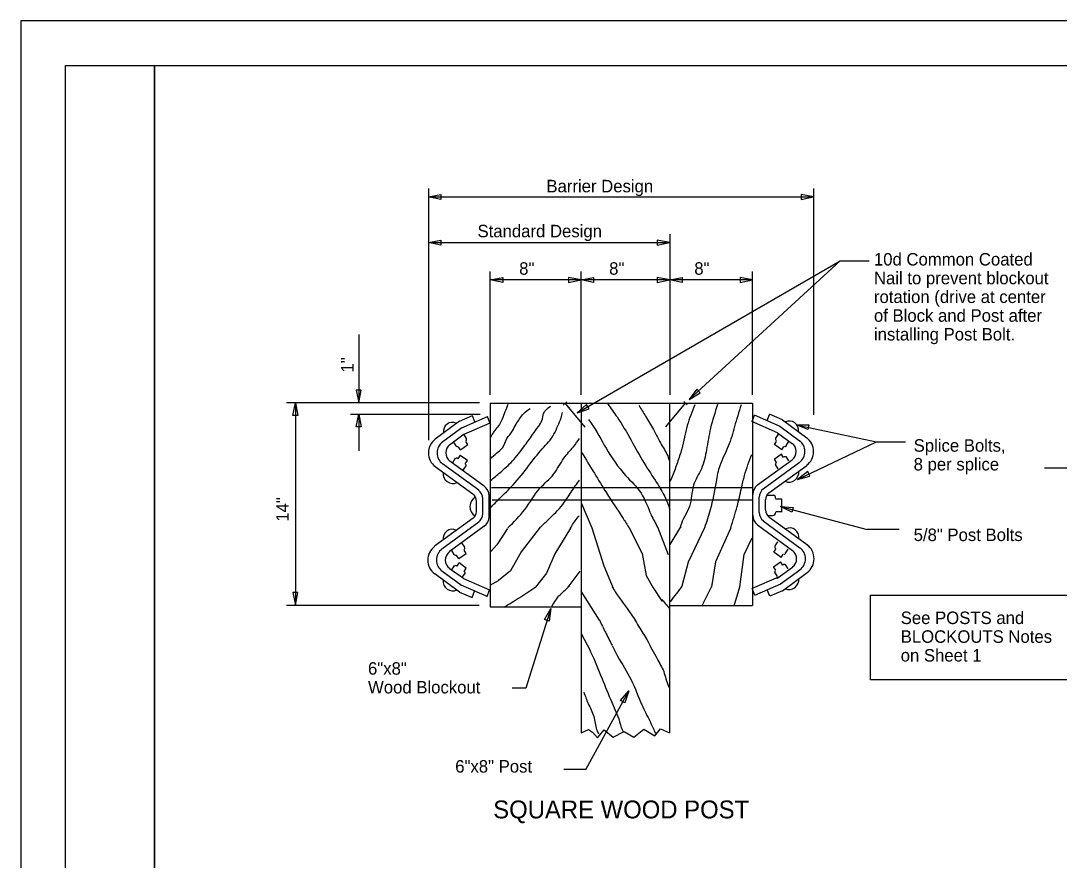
# Model space of a CAD drawing. Extents: x 0 to 34, y 0 to 22.
# Drawn here: x 0 to 11.64, y 12.6 to 22 of the extents above; entities that cross this region are included whole.
import ezdxf

# ---------------------------------------------------------------- set-up
doc = ezdxf.new("R2010")
doc.units = 0
for name, color, linetype in [('SH_Border', 7, 'Continuous'), ('SH_Cut_Line', 7, 'Continuous'), ('ST_Details', 7, 'Continuous'), ('ST_Text', 7, 'Continuous')]:
    doc.layers.add(name, color=color, linetype=linetype)

msp = doc.modelspace()

# ---------------------------------------------------------------- linework, layer by layer
at = {"layer": 'SH_Border'}
for points in [[(0.5, 21.5), (1.5, 21.5), (1.5, 0.5), (0.5, 0.5)], [(1.5, 21.5), (33.5, 21.5), (33.5, 0.5), (1.5, 0.5)]]:
    msp.add_lwpolyline(points, close=True, dxfattribs=at)
at = {"layer": 'SH_Cut_Line'}
msp.add_lwpolyline([(0, 0), (34, 0), (34, 22), (0, 22)], close=True, dxfattribs=at)
at = {"layer": 'ST_Details'}
for p, q in [((5.261, 17.716), (8.2, 17.716)), ((5.261, 17.716), (5.261, 15.435)), ((6.117, 17.731), (6.076, 17.694)), ((6.099, 17.712), (6.32, 17.447)), ((6.279, 17.716), (6.279, 14.022)), ((7.446, 17.717), (7.226, 17.452)), ((7.271, 17.716), (7.271, 14.022)), ((7.428, 17.736), (7.469, 17.699)), ((8.2, 17.716), (8.2, 15.448)), ((4.916, 17.513), (5.06, 17.576)), ((5.088, 17.506), (5.061, 17.575)), ((8.194, 17.511), (8.221, 17.581)), ((8.51, 17.455), (8.22, 17.582)), ((8.363, 17.521), (8.39, 17.59)), ((8.534, 17.528), (8.39, 17.591)), ((4.917, 17.513), (4.644, 17.313)), ((4.941, 17.44), (5.231, 17.566)), ((4.97, 17.369), (5.26, 17.496)), ((5.257, 17.496), (5.23, 17.565)), ((8.48, 17.385), (8.191, 17.511)), ((8.507, 17.457), (8.737, 17.288)), ((8.534, 17.528), (8.807, 17.328)), ((4.944, 17.441), (4.714, 17.273)), ((4.969, 17.369), (4.803, 17.247)), ((4.994, 17.321), (4.964, 17.368)), ((8.461, 17.323), (8.491, 17.37)), ((8.481, 17.384), (8.648, 17.262)), ((4.878, 17.238), (4.849, 17.284)), ((4.927, 17.192), (4.904, 17.228)), ((4.927, 17.192), (5.009, 17.251)), ((5.009, 17.251), (4.986, 17.286)), ((8.446, 17.253), (8.468, 17.288)), ((8.528, 17.194), (8.446, 17.253)), ((8.528, 17.194), (8.551, 17.23)), ((8.577, 17.24), (8.606, 17.286)), ((4.901, 17.093), (4.926, 17.132)), ((5.004, 17.074), (4.925, 17.131)), ((8.443, 17.089), (8.522, 17.146)), ((8.546, 17.108), (8.522, 17.147)), ((8.606, 17.068), (8.575, 17.118)), ((5.067, 16.696), (4.644, 17.004)), ((5.131, 16.741), (4.727, 17.035)), ((5.194, 16.786), (4.809, 17.066)), ((4.841, 17.053), (4.873, 17.103)), ((4.959, 16.967), (4.99, 17.015)), ((4.98, 17.035), (5.004, 17.073)), ((8.257, 16.801), (8.642, 17.081)), ((8.32, 16.756), (8.724, 17.05)), ((8.383, 16.711), (8.807, 17.019)), ((8.468, 17.051), (8.444, 17.088)), ((8.488, 16.982), (8.457, 17.03)), ((5.276, 16.77), (8.201, 16.77)), ((5.176, 16.475), (5.176, 16.648)), ((5.247, 16.445), (5.247, 16.678)), ((8.203, 16.46), (8.203, 16.693)), ((8.274, 16.49), (8.274, 16.663)), ((8.361, 16.684), (8.433, 16.684)), ((8.456, 16.643), (8.529, 16.643)), ((8.529, 16.503), (8.529, 16.642)), ((5.106, 16.504), (5.106, 16.618)), ((5.176, 16.556), (5.176, 16.567)), ((5.284, 16.634), (8.197, 16.634)), ((6.282, 16.59), (6.399, 16.321)), ((8.274, 16.571), (8.274, 16.582)), ((8.317, 16.632), (8.317, 16.632)), ((8.345, 16.519), (8.345, 16.634)), ((5.068, 16.427), (4.637, 16.112)), ((8.362, 16.459), (8.424, 16.459)), ((8.383, 16.442), (8.814, 16.127)), ((8.459, 16.503), (8.533, 16.503)), ((5.131, 16.382), (4.72, 16.081)), ((5.194, 16.337), (4.802, 16.05)), ((7.133, 16.33), (7.256, 16.019)), ((7.393, 16.33), (7.274, 16.133)), ((8.257, 16.353), (8.649, 16.065)), ((8.32, 16.398), (8.731, 16.096)), ((4.858, 16.02), (4.829, 16.066)), ((4.974, 16.103), (4.944, 16.15)), ((4.989, 16.033), (4.967, 16.068)), ((8.438, 16.046), (8.461, 16.082)), ((8.453, 16.116), (8.484, 16.163)), ((8.569, 16.034), (8.598, 16.079)), ((4.907, 15.974), (4.884, 16.01)), ((4.907, 15.974), (4.989, 16.033)), ((8.521, 15.988), (8.438, 16.046)), ((8.52, 15.987), (8.544, 16.023)), ((4.938, 15.675), (4.72, 15.834)), ((4.96, 15.75), (4.802, 15.865)), ((4.829, 15.848), (4.86, 15.898)), ((4.889, 15.888), (4.913, 15.927)), ((4.992, 15.869), (4.913, 15.927)), ((4.968, 15.831), (4.991, 15.868)), ((6.146, 15.669), (6.269, 15.835)), ((8.436, 15.882), (8.514, 15.94)), ((8.46, 15.844), (8.436, 15.881)), ((8.473, 15.753), (8.648, 15.88)), ((8.513, 15.691), (8.731, 15.849)), ((8.539, 15.901), (8.514, 15.94)), ((8.599, 15.861), (8.567, 15.911)), ((4.917, 15.599), (4.638, 15.803)), ((4.947, 15.762), (4.978, 15.81)), ((4.96, 15.751), (5.254, 15.623)), ((5.259, 15.678), (5.354, 15.729)), ((8.491, 15.766), (8.197, 15.638)), ((8.481, 15.775), (8.45, 15.823)), ((8.534, 15.615), (8.813, 15.818)), ((4.915, 15.6), (5.059, 15.537)), ((5.226, 15.549), (4.936, 15.676)), ((5.058, 15.538), (5.086, 15.61)), ((5.225, 15.549), (5.253, 15.623)), ((6.485, 15.285), (6.278, 15.611)), ((7.077, 15.66), (7.188, 15.495)), ((7.634, 15.448), (7.739, 15.66)), ((7.994, 15.444), (8.057, 15.66)), ((8.226, 15.565), (8.197, 15.638)), ((8.225, 15.565), (8.515, 15.691)), ((8.393, 15.553), (8.365, 15.626)), ((8.536, 15.615), (8.392, 15.553)), ((5.261, 15.435), (6.278, 15.435)), ((7.27, 15.448), (8.199, 15.448)), ((6.278, 15.137), (6.379, 14.944)), ((6.619, 14.373), (6.703, 14.178))]:
    msp.add_line(p, q, dxfattribs=at)
for points in [[(5.453, 16.313), (5.335, 16.129), (5.264, 16.05)], [(5.819, 16.325), (5.607, 16.05), (5.488, 15.839), (5.354, 15.729)], [(6.16, 16.315), (5.984, 16.028), (5.892, 15.813), (5.768, 15.656)], [(6.399, 16.321), (6.532, 15.892), (6.637, 15.642)], [(6.816, 16.321), (6.962, 16.032), (7.006, 15.787), (7.086, 15.647)], [(7.662, 16.321), (7.48, 15.936), (7.409, 15.665)], [(7.955, 16.321), (7.783, 15.94), (7.739, 15.66)], [(8.057, 15.66), (8.107, 16.019), (8.195, 16.208)], [(6.279, 14.022), (6.36, 14.06), (6.406, 14.03), (6.464, 13.968), (6.538, 14.056), (6.638, 13.973), (6.762, 14.038), (6.869, 13.973), (6.981, 14.065), (7.105, 13.99), (7.167, 14.069), (7.271, 14.022)]]:
    msp.add_lwpolyline(points, dxfattribs=at)
for centre, major_axis, start_param, end_param in [((4.836, 17.394), (0, -0.107), 2.687211, 4.851441), ((8.614, 17.409), (0, -0.107), 1.431744, 3.595974), ((4.745, 17.159), (0, -0.187), 3.747084, 5.680264), ((4.807, 17.159), (0, -0.15), 3.747137, 5.680324), ((4.869, 17.159), (0, -0.112), 3.747102, 5.680297), ((4.891, 17.249), (0, -0.0195), 5.247458, 6.879592), ((4.978, 17.309), (0, 0.0198), 3.70437, 5.352473), ((8.477, 17.311), (0, 0.0198), 0.930712, 2.578815), ((8.564, 17.251), (0, -0.0195), 5.686779, 7.318912), ((8.582, 17.174), (0, -0.112), 0.602888, 2.536083), ((8.644, 17.174), (0, -0.15), 0.602861, 2.536048), ((8.706, 17.174), (0, -0.187), 0.602921, 2.536101), ((8.562, 17.095), (0, 0.021), 5.448045, 7.11407), ((4.885, 17.079), (0, 0.021), 5.452301, 7.118326), ((4.971, 17.017), (0, 0.021), 4.196406, 5.73538), ((8.477, 17.032), (0, 0.021), 0.547805, 2.086779), ((4.84, 16.931), (0, -0.115), 4.640651, 6.714317), ((8.611, 16.946), (0, -0.115), 5.852054, 7.925719), ((5.123, 16.678), (0, 0.131), 4.712389, 5.680267), ((8.327, 16.693), (0, 0.131), 0.602918, 1.570796), ((5.146, 16.556), (0, -0.12), 3.613765, 5.74142), ((5.017, 16.619), (0, 0.0937), 4.712389, 5.680377), ((5.07, 16.648), (0, 0.112), 4.712389, 5.68034), ((8.381, 16.663), (0, 0.112), 0.602846, 1.570796), ((8.434, 16.634), (0, 0.0937), 0.602808, 1.570796), ((8.431, 16.654), (0, -0.0298), 2.729343, 3.43401), ((8.43, 16.654), (0, 0.03), 4.574534, 6.237266), ((8.431, 16.654), (0, -0.0298), 1.431351, 1.439211), ((5.017, 16.504), (0, -0.0937), 0.605563, 1.570796), ((5.07, 16.475), (0, -0.112), 0.605651, 1.570796), ((5.123, 16.445), (0, -0.131), 0.605566, 1.570796), ((8.327, 16.46), (0, -0.131), 4.712389, 5.677619), ((8.381, 16.49), (0, -0.112), 4.712389, 5.677535), ((8.434, 16.519), (0, -0.0937), 4.712389, 5.677623), ((8.429, 16.491), (0, -0.0326), 6.093782, 8.000338), ((4.833, 16.197), (0, -0.107), 2.687211, 4.851441), ((8.618, 16.212), (0, -0.107), 1.431744, 3.595974), ((4.738, 15.957), (0, -0.187), 3.747091, 5.68028), ((4.8, 15.958), (0, -0.15), 3.747115, 5.680355), ((4.958, 16.091), (0, 0.0198), 3.70437, 5.352473), ((8.469, 16.104), (0, 0.0198), 0.930712, 2.578815), ((8.588, 15.973), (0, -0.112), 0.602927, 2.536083), ((8.651, 15.973), (0, -0.15), 0.602831, 2.53607), ((8.713, 15.973), (0, -0.187), 0.602905, 2.536094), ((4.863, 15.958), (0, -0.112), 3.747102, 5.680258), ((4.871, 16.031), (0, -0.0195), 5.247458, 6.879592), ((8.556, 16.044), (0, -0.0195), 5.686779, 7.318912), ((4.873, 15.875), (0, 0.021), 5.452301, 7.118326), ((4.959, 15.812), (0, 0.021), 4.196406, 5.73538), ((8.469, 15.825), (0, 0.021), 0.547805, 2.086779), ((8.555, 15.888), (0, 0.021), 5.448045, 7.11407), ((4.84, 15.728), (0, -0.115), 4.640651, 6.714317), ((8.611, 15.743), (0, -0.115), 5.852054, 7.925719)]:
    msp.add_ellipse(centre, major_axis=major_axis, ratio=0.944544, start_param=start_param, end_param=end_param, dxfattribs=at)
for points in [[(5.456, 17.702), (5.393, 17.536), (5.364, 17.478), (5.321, 17.42), (5.292, 17.382), (5.259, 17.324)], [(6.577, 17.707), (6.682, 17.561), (6.838, 17.303), (6.987, 17.042), (7.125, 16.826), (7.216, 16.669), (7.274, 16.526)], [(6.926, 17.69), (7.002, 17.569), (7.089, 17.419), (7.18, 17.249), (7.256, 17.107), (7.267, 17.069)], [(7.552, 17.698), (7.469, 17.466), (7.407, 17.203), (7.357, 17.05), (7.303, 16.901), (7.27, 16.831)], [(7.808, 17.7), (7.729, 17.435), (7.684, 17.194), (7.626, 16.98), (7.539, 16.796), (7.493, 16.56), (7.394, 16.337), (7.391, 16.321)], [(8.071, 17.698), (7.998, 17.453), (7.928, 17.234), (7.833, 17.015), (7.791, 16.836), (7.725, 16.52), (7.662, 16.321)], [(5.263, 16.851), (5.372, 16.94), (5.51, 17.07), (5.637, 17.228), (5.735, 17.363), (5.8, 17.455), (5.84, 17.52), (5.858, 17.601), (5.935, 17.682)], [(5.263, 17.094), (5.332, 17.155), (5.397, 17.217), (5.448, 17.32), (5.51, 17.405), (5.55, 17.482), (5.59, 17.54), (5.633, 17.597), (5.709, 17.658)], [(5.266, 16.547), (5.364, 16.647), (5.517, 16.801), (5.691, 17.013), (5.844, 17.205), (5.975, 17.367), (6.018, 17.463), (6.055, 17.551), (6.072, 17.613)], [(6.362, 17.533), (6.392, 17.492), (6.559, 17.211), (6.777, 16.907), (6.951, 16.707), (7.064, 16.465), (7.137, 16.321)], [(5.459, 16.321), (5.648, 16.524), (5.818, 16.763), (5.971, 16.92), (6.087, 17.101), (6.193, 17.228), (6.262, 17.32)], [(6.283, 17.165), (6.428, 16.93), (6.562, 16.711), (6.751, 16.423), (6.816, 16.321)], [(7.955, 16.321), (8.027, 16.56), (8.076, 16.761), (8.11, 16.906), (8.192, 17.142)], [(5.815, 16.321), (5.909, 16.409), (6.073, 16.582), (6.167, 16.72), (6.262, 16.855)], [(6.16, 16.315), (6.174, 16.34), (6.258, 16.455)], [(5.415, 15.432), (5.593, 15.54), (5.773, 15.66)], [(5.953, 15.443), (6.044, 15.57), (6.134, 15.655), (6.151, 15.675)], [(6.625, 15.66), (6.662, 15.601), (6.84, 15.352), (6.933, 15.199)], [(7.409, 15.665), (7.378, 15.623), (7.312, 15.54), (7.278, 15.492)], [(7.184, 15.515), (7.234, 15.457), (7.271, 15.415)], [(6.484, 15.287), (6.551, 15.15), (6.626, 15.003)], [(6.924, 15.214), (7.014, 15.067), (7.13, 14.853), (7.204, 14.708), (7.258, 14.546), (7.27, 14.524)], [(6.375, 14.951), (6.385, 14.931), (6.513, 14.629), (6.622, 14.365)], [(6.627, 15.001), (6.687, 14.883), (6.84, 14.616), (6.96, 14.336), (7.051, 14.148), (7.092, 14.06), (7.121, 14.003)], [(6.309, 14.478), (6.358, 14.351), (6.42, 14.207), (6.453, 14.058), (6.474, 14.01)], [(6.703, 14.178), (6.741, 14.051), (6.753, 14.025)]]:
    msp.add_spline(points, degree=3, dxfattribs=at)
at = {"layer": 'ST_Text'}
for p, q in [((4.567, 20.121), (4.567, 17.7)), ((4.567, 20.027), (7.282, 20.027)), ((7.282, 20.027), (8.884, 20.027)), ((8.884, 20.121), (8.884, 17.585)), ((7.272, 19.61), (7.272, 19.064)), ((7.272, 19.61), (7.272, 17.81)), ((4.567, 19.515), (6.666, 19.515)), ((6.666, 19.515), (7.272, 19.515)), ((7.49, 17.757), (9.181, 19.312)), ((9.181, 19.312), (9.508, 19.312)), ((5.261, 17.81), (5.261, 19.191)), ((8.2, 19.097), (5.261, 19.097)), ((6.279, 17.81), (6.279, 19.191)), ((8.2, 17.81), (8.2, 19.191)), ((3.788, 18.484), (3.788, 17.723)), ((2.978, 17.723), (5.139, 17.723)), ((3.077, 17.718), (3.077, 16.996)), ((4.567, 17.7), (4.567, 17.569)), ((3.694, 17.592), (5.149, 17.592)), ((3.788, 17.592), (3.788, 17.183)), ((4.567, 17.569), (4.567, 17.303)), ((8.687, 17.475), (9.587, 17.282)), ((8.704, 16.862), (9.587, 17.282)), ((9.587, 17.282), (9.912, 17.282)), ((3.077, 16.996), (3.077, 15.453)), ((8.514, 16.559), (9.485, 16.299)), ((9.841, 16.299), (9.485, 16.299)), ((2.978, 15.453), (5.135, 15.453)), ((5.939, 15.417), (5.659, 14.523)), ((5.659, 14.523), (5.507, 14.523)), ((6.332, 13.611), (6.814, 14.493)), ((6.332, 13.611), (6.085, 13.611))]:
    msp.add_line(p, q, dxfattribs=at)
for points in [[(4.707, 19.999), (4.567, 20.027), (4.707, 20.055)], [(8.744, 19.999), (8.884, 20.027), (8.744, 20.055)], [(4.707, 19.487), (4.567, 19.515), (4.707, 19.543)], [(7.132, 19.487), (7.272, 19.515), (7.132, 19.543)], [(5.401, 19.069), (5.261, 19.097), (5.401, 19.125)], [(6.139, 19.069), (6.279, 19.097), (6.139, 19.125)], [(6.419, 19.069), (6.279, 19.097), (6.419, 19.125)], [(7.132, 19.069), (7.272, 19.097), (7.132, 19.125)], [(7.412, 19.069), (7.272, 19.097), (7.412, 19.125)], [(8.06, 19.069), (8.2, 19.097), (8.06, 19.125)], [(3.76, 17.863), (3.788, 17.723), (3.816, 17.863)], [(7.575, 17.871), (7.49, 17.757), (7.613, 17.83)], [(3.049, 17.578), (3.077, 17.718), (3.105, 17.578)], [(6.34, 17.701), (6.233, 17.607), (6.368, 17.652)], [(3.76, 17.452), (3.788, 17.592), (3.816, 17.452)], [(8.818, 17.419), (8.687, 17.475), (8.829, 17.474)], [(8.818, 16.949), (8.704, 16.862), (8.842, 16.899)], [(8.641, 16.494), (8.514, 16.559), (8.656, 16.548)], [(3.049, 15.593), (3.077, 15.453), (3.105, 15.593)], [(9.52, 15.565), (12.305, 15.565), (12.305, 14.616), (9.52, 14.616)], [(5.869, 15.293), (5.939, 15.417), (5.922, 15.275)], [(6.719, 14.386), (6.814, 14.493), (6.768, 14.358)]]:
    msp.add_lwpolyline(points, close=True, dxfattribs=at)
for points in [[(6.233, 17.607), (9.181, 19.312)], [(13.304, 17.476), (11.724, 16.986), (11.473, 16.986)]]:
    msp.add_lwpolyline(points, dxfattribs=at)

# ---------------------------------------------------------------- texts
for s, rotation, p in [('Barrier Design', 360, (5.89, 20.078)), ('Standard Design', 360, (5.118, 19.574)), ('10d Common Coated', 360, (9.56, 19.258)), ('  8"', 360, (5.481, 19.155)), ('  8"', 360, (6.489, 19.155)), ('  8"', 360, (7.443, 19.155)), ('Nail to prevent blockout', 360, (9.56, 19.048)), ('rotation (drive at center', 360, (9.56, 18.838)), ('of Block and Post after', 360, (9.56, 18.628)), ('installing Post Bolt.', 360, (9.56, 18.418)), ('1"', 90, (3.729, 18.059)), ('Splice Bolts,', 360, (10.005, 17.172)), ('8 per splice', 360, (10.005, 16.962)), ('14" ', 90, (3.002, 16.388)), ('5/8" Post Bolts', 360, (10.005, 16.171)), ('See POSTS and', 360, (9.86, 15.241)), ('BLOCKOUTS Notes', 360, (9.86, 15.031)), ('on Sheet 1', 360, (9.86, 14.821)), ('6"x8"', 360, (3.891, 14.674)), ('Wood Blockout', 360, (3.891, 14.464)), ('6"x8" Post', 360, (4.868, 13.577))]:
    msp.add_text(s, height=0.14, rotation=rotation, dxfattribs=at).set_placement(p)
msp.add_text('SQUARE WOOD POST', height=0.2, dxfattribs=at).set_placement((5.294, 13.064))

doc.saveas('drawing.dxf')
